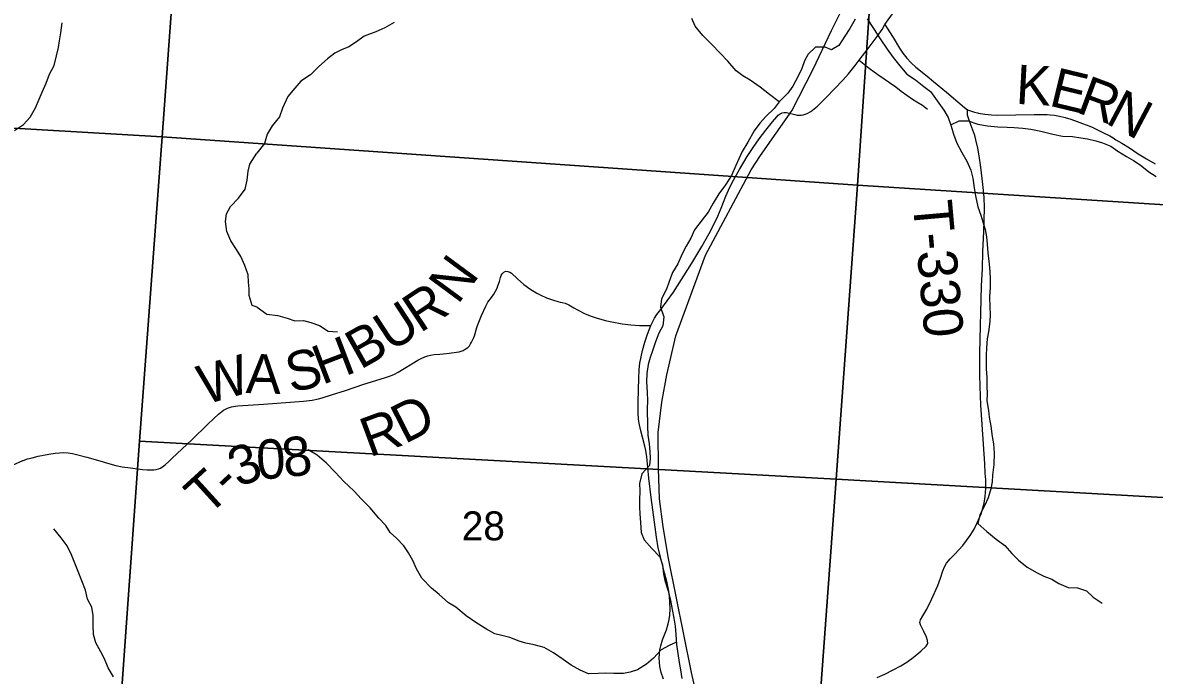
# Model space of a CAD drawing. Extents: x 0 to 34, y 0 to 22.
# Drawn here: x 4.184 to 5.819, y 16.076 to 17.019 of the extents above; entities that cross this region are included whole.
import ezdxf

# ---------------------------------------------------------------- set-up
doc = ezdxf.new("R2010")
doc.units = 0
for name, color, linetype in [('GM_X_Corporation', 7, 'Continuous'), ('GM_X_Major_River', 7, 'Continuous'), ('GM_X_Minor_River', 7, 'Continuous'), ('GM_X_Rail_Line', 7, 'Continuous'), ('GM_X_Section_Text', 7, 'Continuous'), ('GM_X_State_Route', 7, 'Continuous'), ('GM_X_Township_Road', 7, 'Continuous'), ('GM_X_Township_Road_Text', 7, 'Continuous')]:
    doc.layers.add(name, color=color, linetype=linetype)

msp = doc.modelspace()

# ---------------------------------------------------------------- linework, layer by layer
at = {"layer": 'GM_X_Corporation'}
for points in [[(3.4457, 17.9455), (4.4596, 17.8697), (4.3853, 16.8539), (3.3779, 16.9127)], [(4.4596, 17.8697), (5.4592, 17.8072), (5.3901, 16.7843), (4.3853, 16.8539)], [(6.4386, 17.7441), (6.3912, 16.7203), (5.3901, 16.7843), (5.4592, 17.8072)], [(4.3853, 16.8539), (4.3528, 16.4147), (4.3239, 16.0112), (4.31, 15.819), (3.31, 15.8916), (3.3779, 16.9127)], [(5.3901, 16.7843), (5.359, 16.3599), (4.3528, 16.4147), (4.3853, 16.8539)], [(6.3912, 16.7203), (6.3636, 16.3035), (5.359, 16.3599), (5.3901, 16.7843)], [(5.359, 16.3599), (5.3297, 15.9601), (4.3239, 16.0112), (4.3528, 16.4147)], [(6.3636, 16.3035), (6.3352, 15.898), (5.3297, 15.9601), (5.359, 16.3599)]]:
    msp.add_lwpolyline(points, close=True, dxfattribs=at)
at = {"layer": 'GM_X_Major_River'}
msp.add_lwpolyline([(4.1722, 16.8629), (4.185, 16.8717), (4.1948, 16.8824), (4.2027, 16.8961), (4.2076, 16.9086), (4.2121, 16.9185), (4.2181, 16.9317), (4.223, 16.9443), (4.2294, 16.9568), (4.2331, 16.9709), (4.2357, 16.983), (4.2372, 16.9925), (4.2391, 17.0042), (4.2409, 17.0186)], dxfattribs=at)
at = {"layer": 'GM_X_Minor_River'}
for p, q in [((5.1557, 17.0136), (5.1506, 17.0249)), ((5.4038, 17.0246), (5.413, 17.0103)), ((4.6941, 17.0056), (4.6775, 16.9994)), ((4.7073, 17.0114), (4.6941, 17.0056)), ((4.7209, 17.0191), (4.7073, 17.0114)), ((5.1667, 17.0001), (5.1557, 17.0136)), ((5.413, 17.0103), (5.4226, 16.9956)), ((4.6663, 16.9913), (4.6553, 16.984)), ((4.6775, 16.9994), (4.6663, 16.9913)), ((5.1797, 16.9873), (5.1667, 17.0001)), ((5.4226, 16.9956), (5.4329, 16.9805)), ((4.635, 16.9748), (4.6245, 16.9667)), ((4.6448, 16.9798), (4.635, 16.9748)), ((4.6553, 16.984), (4.6448, 16.9798)), ((5.1916, 16.9749), (5.1797, 16.9873)), ((5.2026, 16.9633), (5.1916, 16.9749)), ((5.4329, 16.9805), (5.4417, 16.9685)), ((4.6121, 16.9556), (4.5997, 16.9434)), ((4.6245, 16.9667), (4.6121, 16.9556)), ((5.2149, 16.9493), (5.2026, 16.9633)), ((5.4417, 16.9685), (5.4513, 16.9564)), ((5.4513, 16.9564), (5.4612, 16.9444)), ((4.5997, 16.9434), (4.5858, 16.9342)), ((5.2244, 16.9422), (5.2149, 16.9493)), ((5.235, 16.9359), (5.2244, 16.9422)), ((5.4612, 16.9444), (5.4738, 16.9365)), ((4.5772, 16.9242), (4.5671, 16.912)), ((4.5858, 16.9342), (4.5772, 16.9242)), ((5.2495, 16.9258), (5.235, 16.9359)), ((5.2628, 16.9153), (5.2495, 16.9258)), ((5.4738, 16.9365), (5.486, 16.9268)), ((5.486, 16.9268), (5.4955, 16.9193)), ((4.5671, 16.912), (4.5596, 16.8956)), ((5.2769, 16.9044), (5.2628, 16.9153)), ((5.4955, 16.9193), (5.5051, 16.9061)), ((5.5051, 16.9061), (5.5146, 16.8926)), ((4.5596, 16.8956), (4.5548, 16.8827)), ((5.5146, 16.8926), (5.5208, 16.882)), ((4.5548, 16.8827), (4.5443, 16.8697)), ((5.5208, 16.882), (5.5254, 16.8692)), ((5.5247, 16.8712), (5.5371, 16.8773)), ((5.5371, 16.8773), (5.55, 16.877)), ((5.55, 16.877), (5.564, 16.8722)), ((4.5373, 16.8579), (4.5336, 16.8446)), ((4.5443, 16.8697), (4.5373, 16.8579)), ((5.5254, 16.8692), (5.5289, 16.8579)), ((5.5289, 16.8579), (5.5336, 16.845)), ((5.564, 16.8722), (5.578, 16.8697)), ((5.578, 16.8697), (5.5928, 16.8683)), ((5.5928, 16.8683), (5.6064, 16.868)), ((5.6064, 16.868), (5.6163, 16.8677)), ((5.6163, 16.8677), (5.6291, 16.8667)), ((5.6291, 16.8667), (5.6405, 16.8649)), ((5.6405, 16.8649), (5.6549, 16.862)), ((5.6549, 16.862), (5.6723, 16.858)), ((5.6723, 16.858), (5.6864, 16.8551)), ((4.5336, 16.8446), (4.5224, 16.8306)), ((5.5336, 16.845), (5.5409, 16.8314)), ((5.6864, 16.8551), (5.7007, 16.8545)), ((5.7007, 16.8545), (5.7129, 16.8527)), ((5.7129, 16.8527), (5.7223, 16.8509)), ((5.7223, 16.8509), (5.7345, 16.8484)), ((5.7345, 16.8484), (5.744, 16.8454)), ((5.744, 16.8454), (5.7561, 16.8406)), ((5.7561, 16.8406), (5.766, 16.8335)), ((4.5122, 16.8144), (4.5224, 16.8306)), ((5.5409, 16.8314), (5.5478, 16.819)), ((5.766, 16.8335), (5.7789, 16.8256)), ((5.7789, 16.8256), (5.7888, 16.8197)), ((4.5096, 16.8046), (4.5122, 16.8144)), ((5.5478, 16.819), (5.554, 16.8058)), ((5.7888, 16.8197), (5.7983, 16.8137)), ((5.7983, 16.8137), (5.8109, 16.8036)), ((4.5052, 16.7784), (4.5085, 16.7913)), ((4.5085, 16.7913), (4.5096, 16.8046)), ((5.554, 16.8058), (5.5567, 16.7941)), ((5.5567, 16.7941), (5.5584, 16.7804)), ((5.8109, 16.8036), (5.8216, 16.7969)), ((4.4958, 16.7655), (4.5052, 16.7784)), ((5.5584, 16.7804), (5.5607, 16.7687)), ((4.4844, 16.7533), (4.4958, 16.7655)), ((5.5607, 16.7687), (5.5639, 16.7528)), ((4.4769, 16.7317), (4.4784, 16.743)), ((4.4784, 16.743), (4.4844, 16.7533)), ((5.5639, 16.7528), (5.5682, 16.7411)), ((4.4789, 16.7173), (4.4769, 16.7317)), ((5.5682, 16.7411), (5.5713, 16.7313)), ((5.5713, 16.7313), (5.5744, 16.7203)), ((4.4846, 16.7037), (4.4789, 16.7173)), ((5.5744, 16.7203), (5.5764, 16.7097)), ((5.5764, 16.7097), (5.5772, 16.6991)), ((4.493, 16.6912), (4.4846, 16.7037)), ((5.5772, 16.6991), (5.5781, 16.6866)), ((4.4991, 16.681), (4.493, 16.6912)), ((4.5048, 16.6681), (4.4991, 16.681)), ((5.5781, 16.6866), (5.5801, 16.67)), ((4.5098, 16.6545), (4.5048, 16.6681)), ((5.5801, 16.67), (5.581, 16.6594)), ((4.5102, 16.6443), (4.5098, 16.6545)), ((4.511, 16.6344), (4.5102, 16.6443)), ((5.581, 16.6594), (5.5815, 16.6484)), ((5.5815, 16.6484), (5.5819, 16.6359)), ((4.511, 16.625), (4.511, 16.6344)), ((5.5819, 16.6359), (5.5809, 16.6234)), ((4.5156, 16.6106), (4.511, 16.625)), ((5.5809, 16.6234), (5.5811, 16.6079)), ((4.5227, 16.6079), (4.5156, 16.6106)), ((4.5227, 16.6079), (4.5365, 16.598)), ((4.5365, 16.598), (4.5528, 16.5962)), ((4.5528, 16.5962), (4.5661, 16.5922)), ((5.5811, 16.6079), (5.5815, 16.5973)), ((5.5815, 16.5973), (5.5812, 16.5874)), ((4.5661, 16.5922), (4.5774, 16.5885)), ((4.5774, 16.5885), (4.5899, 16.5886)), ((4.5899, 16.5886), (4.6005, 16.5861)), ((4.6005, 16.5861), (4.6127, 16.5816)), ((4.6127, 16.5816), (4.6252, 16.5734)), ((5.5812, 16.5874), (5.5791, 16.5726)), ((4.6252, 16.5734), (4.6389, 16.5724)), ((5.5773, 16.5624), (5.5763, 16.5495)), ((5.5791, 16.5726), (5.5773, 16.5624)), ((5.5763, 16.5495), (5.576, 16.5388)), ((5.576, 16.5388), (5.5757, 16.529)), ((5.5757, 16.529), (5.5758, 16.5191)), ((5.5758, 16.5191), (5.577, 16.5066)), ((5.577, 16.5066), (5.5771, 16.4938)), ((5.5772, 16.4828), (5.5769, 16.4729)), ((5.5771, 16.4938), (5.5772, 16.4828)), ((5.5769, 16.4729), (5.5793, 16.4589)), ((5.5793, 16.4589), (5.5805, 16.4491)), ((5.5805, 16.4491), (5.5825, 16.4362)), ((5.5825, 16.4362), (5.5846, 16.4211)), ((5.5846, 16.4211), (5.5866, 16.4105)), ((4.6094, 16.3944), (4.5965, 16.4019)), ((5.5866, 16.4105), (5.5874, 16.3972)), ((4.6227, 16.3828), (4.6094, 16.3944)), ((4.6353, 16.37), (4.6227, 16.3828)), ((5.5874, 16.3972), (5.5872, 16.3806)), ((4.6479, 16.3565), (4.6353, 16.37)), ((5.5872, 16.3806), (5.5851, 16.3654)), ((4.6624, 16.343), (4.6479, 16.3565)), ((5.5848, 16.3559), (5.5826, 16.3457)), ((5.5851, 16.3654), (5.5848, 16.3559)), ((4.6735, 16.3306), (4.6624, 16.343)), ((5.5826, 16.3457), (5.5789, 16.3327)), ((4.6861, 16.3182), (4.6735, 16.3306)), ((4.6983, 16.3035), (4.6861, 16.3182)), ((5.5733, 16.3213), (5.5666, 16.308)), ((5.5789, 16.3327), (5.5733, 16.3213)), ((4.7086, 16.2926), (4.6983, 16.3035)), ((5.5666, 16.308), (5.5637, 16.2958)), ((4.2397, 16.2751), (4.2291, 16.2879)), ((4.7148, 16.2828), (4.7086, 16.2926)), ((5.5637, 16.2958), (5.5771, 16.2842)), ((4.2485, 16.2634), (4.2397, 16.2751)), ((4.7243, 16.2746), (4.7148, 16.2828)), ((4.7346, 16.2633), (4.7243, 16.2746)), ((5.5771, 16.2842), (5.5904, 16.273)), ((5.5904, 16.273), (5.603, 16.264)), ((4.2546, 16.2505), (4.2485, 16.2634)), ((4.7415, 16.2535), (4.7346, 16.2633)), ((4.7477, 16.2422), (4.7415, 16.2535)), ((5.603, 16.264), (5.6129, 16.2523)), ((5.6129, 16.2523), (5.6228, 16.2426)), ((4.2592, 16.2384), (4.2546, 16.2505)), ((4.2641, 16.2263), (4.2592, 16.2384)), ((4.7531, 16.2301), (4.7477, 16.2422)), ((5.6228, 16.2426), (5.6354, 16.2325)), ((4.2695, 16.2127), (4.2641, 16.2263)), ((4.7608, 16.2169), (4.7531, 16.2301)), ((5.6354, 16.2325), (5.6495, 16.2246)), ((5.6495, 16.2246), (5.6593, 16.2194)), ((5.6593, 16.2194), (5.6707, 16.2154)), ((4.2748, 16.1994), (4.2695, 16.2127)), ((4.7745, 16.2023), (4.7608, 16.2169)), ((5.6707, 16.2154), (5.681, 16.209)), ((5.681, 16.209), (5.6943, 16.2034)), ((5.6943, 16.2034), (5.7079, 16.2028)), ((5.7079, 16.2028), (5.7208, 16.1984)), ((4.2775, 16.1866), (4.2748, 16.1994)), ((4.284, 16.1749), (4.2775, 16.1866)), ((4.7856, 16.1929), (4.7745, 16.2023)), ((4.7993, 16.1809), (4.7856, 16.1929)), ((5.7208, 16.1984), (5.7307, 16.1894)), ((5.7307, 16.1894), (5.7433, 16.1808)), ((4.2859, 16.1627), (4.284, 16.1749)), ((4.8099, 16.1746), (4.7993, 16.1809)), ((4.8248, 16.1622), (4.8099, 16.1746)), ((4.286, 16.1491), (4.2859, 16.1627)), ((4.8389, 16.1528), (4.8248, 16.1622)), ((4.2864, 16.1355), (4.286, 16.1491)), ((4.8541, 16.1431), (4.8389, 16.1528)), ((4.8659, 16.1364), (4.8541, 16.1431)), ((4.2895, 16.1233), (4.2864, 16.1355)), ((4.2967, 16.1105), (4.2895, 16.1233)), ((4.8761, 16.1339), (4.8659, 16.1364)), ((4.8879, 16.1309), (4.8761, 16.1339)), ((4.9015, 16.1258), (4.8879, 16.1309)), ((4.911, 16.1228), (4.9015, 16.1258)), ((4.9228, 16.1203), (4.911, 16.1228)), ((5.1284, 16.1242), (5.118, 16.1194)), ((4.302, 16.1003), (4.2967, 16.1105)), ((4.9376, 16.1166), (4.9228, 16.1203)), ((4.9509, 16.1091), (4.9376, 16.1166)), ((4.9646, 16.0994), (4.9509, 16.1091)), ((5.1063, 16.1132), (5.0951, 16.1014)), ((5.118, 16.1194), (5.1063, 16.1132)), ((4.3074, 16.087), (4.302, 16.1003)), ((4.9764, 16.0912), (4.9646, 16.0994)), ((4.9893, 16.0837), (4.9764, 16.0912)), ((5.0853, 16.0926), (5.0722, 16.0845)), ((5.0951, 16.1014), (5.0853, 16.0926)), ((4.3154, 16.0742), (4.3074, 16.087)), ((5.0015, 16.0785), (4.9893, 16.0837)), ((5.0155, 16.079), (5.0015, 16.0785)), ((5.0264, 16.0795), (5.0155, 16.079)), ((5.0382, 16.0789), (5.0264, 16.0795)), ((5.0518, 16.079), (5.0382, 16.0789)), ((5.0616, 16.081), (5.0518, 16.079)), ((5.0722, 16.0845), (5.0616, 16.081))]:
    msp.add_line(p, q, dxfattribs=at)
for points in [[(5.3867, 17.024), (5.3789, 17.0103), (5.3718, 16.9993), (5.3632, 16.9859), (5.3527, 16.9798), (5.3432, 16.9835), (5.3296, 16.9837), (5.3187, 16.9734), (5.3135, 16.9635), (5.3098, 16.9529), (5.3042, 16.9414), (5.2968, 16.927), (5.2893, 16.9171), (5.2769, 16.9044), (5.2698, 16.8949), (5.2582, 16.8838), (5.2488, 16.8735), (5.241, 16.8628), (5.2316, 16.8461), (5.2234, 16.8327), (5.2186, 16.8224), (5.2145, 16.8126), (5.2082, 16.7981), (5.1993, 16.7848), (5.1899, 16.7718), (5.1813, 16.7584), (5.1743, 16.7451), (5.1657, 16.734), (5.1544, 16.7195), (5.1492, 16.7078), (5.1425, 16.6959), (5.1366, 16.6849), (5.1306, 16.6704), (5.1228, 16.6583), (5.1173, 16.6438), (5.1143, 16.6339), (5.1069, 16.6202), (5.1055, 16.6081), (5.1101, 16.5941), (5.1087, 16.5812), (5.1031, 16.5705), (5.0983, 16.558), (5.0939, 16.5451), (5.0906, 16.5352), (5.0876, 16.5253), (5.0859, 16.5124), (5.0852, 16.5003), (5.0861, 16.4855), (5.0866, 16.4726), (5.0863, 16.4616), (5.0865, 16.4363), (5.087, 16.4234), (5.089, 16.4105), (5.0899, 16.3995), (5.0903, 16.3897), (5.0897, 16.3794), (5.0784, 16.3676), (5.0751, 16.3535), (5.0756, 16.3426), (5.075, 16.3293), (5.075, 16.3194), (5.0755, 16.3096), (5.0764, 16.2971), (5.0776, 16.2827), (5.0819, 16.2721)], [(5.0819, 16.2721), (5.093, 16.2597), (5.1044, 16.2477), (5.1083, 16.236), (5.1096, 16.2231), (5.1119, 16.2133), (5.1166, 16.1982), (5.1201, 16.1846), (5.1221, 16.1713), (5.1249, 16.1589), (5.1265, 16.1475), (5.1277, 16.1354), (5.1286, 16.121), (5.1306, 16.1078), (5.1326, 16.0949), (5.1342, 16.0843), (5.1362, 16.0718)]]:
    msp.add_lwpolyline(points, dxfattribs=at)
at = {"layer": 'GM_X_Rail_Line'}
msp.add_lwpolyline([(5.593, 15.2957), (5.5443, 15.3738), (5.4839, 15.4718), (5.4022, 15.5773), (5.2476, 15.8396), (5.2185, 15.8919), (5.1864, 15.9607), (5.1627, 16.025), (5.15, 16.0803), (5.1168, 16.245), (5.1092, 16.2909), (5.1042, 16.3311), (5.1027, 16.3749), (5.102, 16.427), (5.1075, 16.471), (5.1144, 16.5104), (5.1278, 16.5666), (5.1707, 16.683), (5.2365, 16.8064), (5.25, 16.827), (5.2951, 16.8915), (5.3262, 16.9519), (5.3526, 17.0073), (5.3847, 17.0725)], dxfattribs=at)
at = {"layer": 'GM_X_State_Route'}
for points in [[(5.3037, 16.8854), (5.3057, 16.8852), (5.3086, 16.8853), (5.3116, 16.8858), (5.3144, 16.8866), (5.3172, 16.8878), (5.3225, 16.8907), (5.3275, 16.8943), (5.3322, 16.8982), (5.3453, 16.9114), (5.3688, 16.9359), (5.3771, 16.9451), (5.3868, 16.9571), (5.3926, 16.9646), (5.4056, 16.9816), (5.4185, 16.9989), (5.4255, 17.009), (5.4297, 17.016), (5.4429, 17.0352)], [(5.1099, 16.0709), (5.1064, 16.0804), (5.1044, 16.0892), (5.1038, 16.0953), (5.1036, 16.1013), (5.104, 16.1075), (5.1047, 16.1132), (5.1059, 16.1191), (5.1085, 16.1278), (5.114, 16.1422), (5.1167, 16.151), (5.1179, 16.157), (5.1187, 16.1631), (5.1192, 16.1723), (5.1191, 16.1816), (5.1185, 16.1902), (5.1175, 16.198), (5.1152, 16.2098), (5.1114, 16.2246), (5.1057, 16.2456), (5.1023, 16.2607), (5.0996, 16.2761), (5.0967, 16.2977), (5.0922, 16.3334), (5.0887, 16.361), (5.0855, 16.3919), (5.0841, 16.401), (5.0829, 16.4071), (5.0768, 16.4312), (5.0748, 16.4404), (5.0739, 16.4465), (5.0733, 16.4556), (5.0732, 16.4711), (5.0741, 16.5053), (5.0747, 16.5178), (5.0757, 16.5271), (5.0773, 16.5363), (5.0794, 16.5454), (5.0828, 16.5574), (5.0868, 16.5692), (5.0916, 16.5814), (5.0939, 16.5866), (5.0968, 16.5921), (5.1002, 16.5974), (5.1058, 16.6049), (5.1153, 16.6172), (5.1242, 16.6298), (5.1508, 16.6718), (5.1652, 16.6957), (5.1759, 16.7145), (5.1831, 16.7282), (5.1885, 16.7394), (5.1931, 16.7508), (5.1998, 16.7682), (5.2035, 16.7768), (5.2091, 16.7879), (5.2197, 16.8069), (5.2307, 16.8256), (5.2392, 16.8386), (5.2482, 16.8512), (5.2577, 16.8636), (5.2672, 16.8758), (5.2733, 16.8829), (5.2755, 16.8852), (5.2781, 16.8872), (5.2811, 16.8886), (5.2843, 16.8892), (5.2876, 16.889), (5.2938, 16.8877), (5.2997, 16.8861), (5.3027, 16.8855), (5.3037, 16.8854)]]:
    msp.add_lwpolyline(points, dxfattribs=at)
at = {"layer": 'GM_X_Township_Road'}
for points in [[(5.4297, 17.016), (5.4364, 17.0054), (5.4414, 16.9976), (5.4508, 16.9821), (5.4557, 16.9747), (5.4612, 16.9674), (5.4675, 16.9607), (5.4743, 16.9546), (5.4907, 16.9415), (5.4999, 16.9341), (5.5184, 16.9185), (5.5348, 16.9043), (5.5446, 16.8964), (5.5491, 16.8931), (5.5535, 16.8914), (5.5591, 16.8898), (5.5636, 16.8886), (5.565, 16.8882), (5.5742, 16.8867), (5.5834, 16.8859), (5.5927, 16.8855), (5.6187, 16.8857), (5.6454, 16.8862), (5.664, 16.8862), (5.6683, 16.8858), (5.6746, 16.8851), (5.6818, 16.8839), (5.6901, 16.8819), (5.6984, 16.8793), (5.7072, 16.8763), (5.728, 16.8683), (5.7452, 16.8599), (5.7545, 16.8554), (5.7594, 16.8525), (5.7631, 16.8499), (5.7721, 16.8448), (5.7829, 16.8379), (5.7955, 16.8295), (5.8074, 16.8221), (5.8201, 16.8148)], [(5.3926, 16.9646), (5.3972, 16.9609), (5.407, 16.9531), (5.4196, 16.9439), (5.4453, 16.926), (5.4532, 16.9197), (5.4693, 16.9082), (5.4757, 16.9043), (5.4838, 16.8995), (5.4889, 16.896), (5.4913, 16.894)], [(5.567, 16.5427), (5.5673, 16.5603), (5.5677, 16.5818), (5.568, 16.5996), (5.5687, 16.619), (5.5694, 16.6388), (5.5704, 16.6636), (5.571, 16.6885), (5.5726, 16.717), (5.5731, 16.7336), (5.5736, 16.7517), (5.5732, 16.767), (5.5716, 16.7806), (5.5701, 16.794), (5.5681, 16.8102), (5.5659, 16.8264), (5.5638, 16.8377), (5.5612, 16.8499), (5.5595, 16.8558), (5.5539, 16.8711), (5.5509, 16.8793), (5.5491, 16.8852), (5.5488, 16.8894), (5.5491, 16.8931)], [(4.1692, 16.3798), (4.1844, 16.3864), (4.1848, 16.3866), (4.1911, 16.3888), (4.1976, 16.3907), (4.2066, 16.3928), (4.2219, 16.3958), (4.2311, 16.3973), (4.2372, 16.3979), (4.2434, 16.398), (4.2496, 16.3976), (4.2558, 16.3968), (4.2618, 16.3955), (4.2769, 16.3916), (4.2955, 16.3859), (4.3066, 16.3826), (4.3186, 16.3795), (4.3278, 16.3777), (4.3397, 16.3758), (4.357, 16.3737), (4.3639, 16.3732), (4.3698, 16.373), (4.3736, 16.373), (4.377, 16.3735), (4.3801, 16.3744), (4.3829, 16.3756), (4.3881, 16.379), (4.3905, 16.3809), (4.3952, 16.3851), (4.3995, 16.3895), (4.4288, 16.417), (4.4511, 16.4384), (4.46, 16.4471), (4.4668, 16.4535), (4.4716, 16.4574), (4.4742, 16.4591), (4.4769, 16.4606), (4.4797, 16.462), (4.4826, 16.4631), (4.4856, 16.464), (4.4886, 16.4647), (4.4916, 16.4652), (4.4947, 16.4655), (4.5318, 16.4678), (4.5897, 16.4721), (4.602, 16.4739), (4.6112, 16.4758), (4.6169, 16.4773), (4.6303, 16.4815), (4.6505, 16.4879), (4.6769, 16.497), (4.7067, 16.5058), (4.7155, 16.5088), (4.7212, 16.5112), (4.7266, 16.514), (4.7547, 16.5313), (4.7598, 16.5338), (4.7652, 16.5362), (4.7693, 16.5376), (4.7734, 16.5386), (4.7786, 16.5395), (4.7866, 16.5402), (4.7962, 16.541), (4.8147, 16.5437), (4.8177, 16.5445), (4.8206, 16.5456), (4.8235, 16.5472), (4.8271, 16.5499), (4.8293, 16.5523), (4.831, 16.5549), (4.8325, 16.5576), (4.8357, 16.5642), (4.8366, 16.5668), (4.8399, 16.5789), (4.8409, 16.5816), (4.8468, 16.5959), (4.8529, 16.6093), (4.8562, 16.6154), (4.8612, 16.6219), (4.8645, 16.627), (4.8694, 16.6355), (4.8705, 16.6386), (4.8727, 16.645), (4.8743, 16.651), (4.8754, 16.6539), (4.8769, 16.6564), (4.879, 16.6586), (4.8818, 16.6598), (4.8848, 16.6597), (4.8877, 16.6586), (4.8902, 16.6569), (4.8988, 16.6488), (4.9081, 16.6407), (4.9169, 16.6343), (4.927, 16.6284), (4.9325, 16.6255), (4.9408, 16.6216), (4.9507, 16.6179), (4.957, 16.616), (4.9603, 16.6154), (4.9635, 16.6149), (4.9678, 16.614), (4.973, 16.6113), (4.9802, 16.6071), (4.9855, 16.6042), (4.9966, 16.5986), (5.0051, 16.5951), (5.0139, 16.592), (5.0228, 16.5895), (5.0255, 16.5889), (5.035, 16.5868), (5.0502, 16.5841), (5.0625, 16.5826), (5.0749, 16.5816), (5.0841, 16.5815), (5.0916, 16.5814)], [(5.4184, 16.0733), (5.4293, 16.0779), (5.4417, 16.0842), (5.4525, 16.0901), (5.4611, 16.0956), (5.4703, 16.1022), (5.4814, 16.1113), (5.4893, 16.1185), (5.4917, 16.1226), (5.4914, 16.1269), (5.4899, 16.1317), (5.486, 16.1399), (5.481, 16.1492), (5.4802, 16.1526), (5.4809, 16.1566), (5.4843, 16.1622), (5.49, 16.1719), (5.497, 16.1858), (5.5062, 16.2061), (5.51, 16.2169), (5.5131, 16.2272), (5.5156, 16.2329), (5.5186, 16.2382), (5.5241, 16.2448), (5.5306, 16.2512), (5.5423, 16.2638), (5.5529, 16.2782), (5.5586, 16.2876), (5.5629, 16.2965), (5.5688, 16.3098), (5.5732, 16.3248), (5.5744, 16.3344), (5.5754, 16.3464), (5.5753, 16.3585), (5.5747, 16.3684), (5.5738, 16.3819), (5.57, 16.4385), (5.5681, 16.4666), (5.5671, 16.4937), (5.567, 16.5106), (5.567, 16.5407), (5.567, 16.5427)]]:
    msp.add_lwpolyline(points, dxfattribs=at)

# ---------------------------------------------------------------- texts
at = {"layer": 'GM_X_Section_Text'}
msp.add_text('28', height=0.04186, rotation=0, dxfattribs=at).set_placement((4.8184, 16.2713))
at = {"layer": 'GM_X_Township_Road_Text'}
for s, height, rotation, p in [('K', 0.0568, 356.8913, (5.6179, 16.9017)), ('E', 0.0568, 346.4481, (5.6651, 16.8994)), ('R', 0.0568, 339.5874, (5.7047, 16.89)), ('N', 0.0568, 332.0696, (5.7467, 16.8745)), ('T-330', 0.05682, 275.0665, (5.4697, 16.76)), ('N', 0.0568, 53.6038, (4.8126, 16.6106)), ('R', 0.0568, 33.6275, (4.7582, 16.5699)), ('U', 0.0568, 33.1411, (4.7159, 16.5423)), ('B', 0.0568, 29.434, (4.6718, 16.5172)), ('H', 0.0568, 20.9103, (4.6167, 16.4955)), ('S', 0.0568, 13.0687, (4.5713, 16.4843)), ('W', 0.0568, 15.573, (4.4467, 16.4669)), ('A', 0.0568, 358.5865, (4.5058, 16.484)), ('D', 0.0568, 26.9886, (4.7357, 16.4098)), ('R', 0.0568, 20.2509, (4.6853, 16.3908)), ('0', 0.0568, 3.1238, (4.5229, 16.3593)), ('8', 0.0568, 7.886, (4.563, 16.3617)), ('3', 0.0568, 22.3677, (4.4955, 16.3471)), ('T', 0.0568, 42.3688, (4.4511, 16.305)), ('-', 0.0568, 42.9144, (4.4829, 16.3341))]:
    msp.add_text(s, height=height, rotation=rotation, dxfattribs=at).set_placement(p)

doc.saveas('drawing.dxf')
